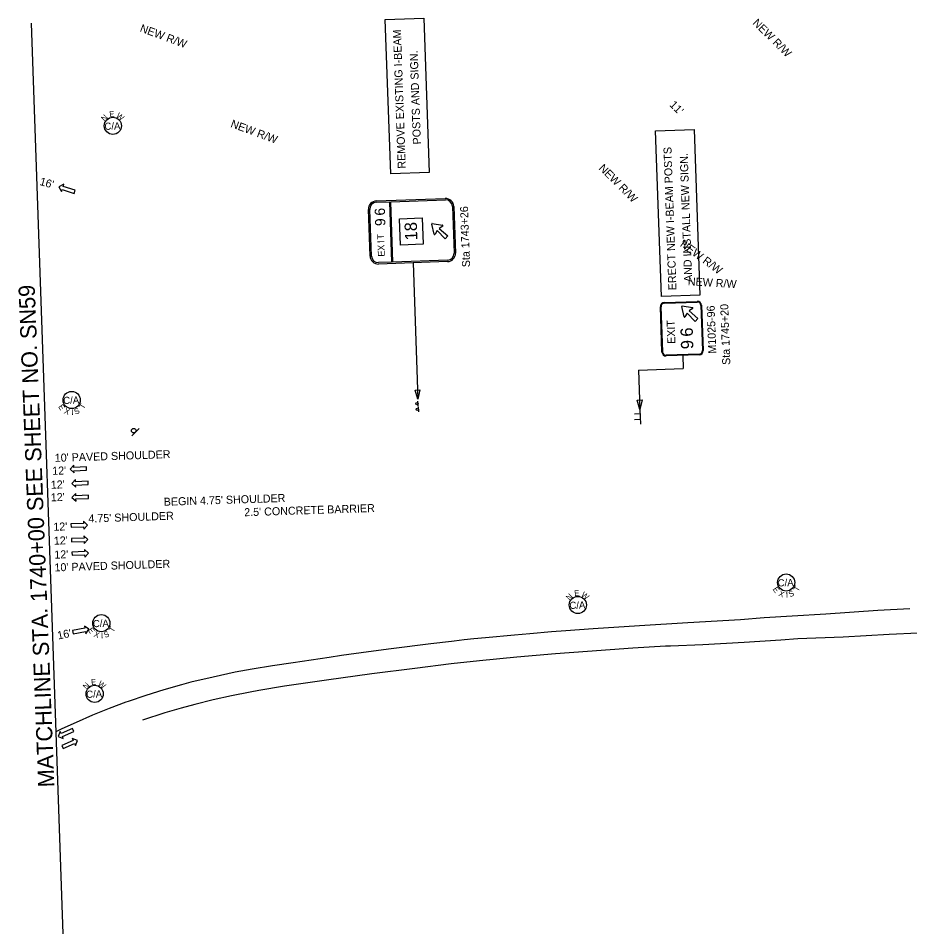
# Model space of a CAD drawing. Extents: x 1820452 to 1822009, y 1192445 to 1193332.
# Drawn here: x 1820452 to 1821231, y 1192445 to 1193246 of the extents above; entities that cross this region are included whole.
import ezdxf

# ---------------------------------------------------------------- set-up
doc = ezdxf.new("R2010")
doc.units = 0
for name, color, linetype in [('RD_EX_Road', 7, 'Continuous'), ('RD_PD_Final_LnLine', 7, 'Continuous'), ('RD_PD_Final_TX', 7, 'Continuous'), ('RD_PD_RW_TX', 7, 'Continuous'), ('RD_SHT_MatchLine', 7, 'Continuous'), ('RD_SHT_TX', 7, 'Continuous'), ('RD_Sketch10', 7, 'Continuous'), ('RD_Sketch8', 7, 'Continuous'), ('SN_P_Signs', 7, 'Continuous')]:
    doc.layers.add(name, color=color, linetype=linetype)

# ---------------------------------------------------------------- blocks, each defined once
blk = doc.blocks.new('SARRW2')
at = {"layer": 'RD_PD_Final_LnLine'}
blk.add_lwpolyline([(-12, 1.2), (-12, -1.2), (-2.83, -1.2), (-2.83, -2.83), (0, 0), (-2.83, 2.83), (-2.83, 1.2)], close=True, dxfattribs=at)

msp = doc.modelspace()

# ---------------------------------------------------------------- linework, layer by layer
at = {"layer": 'RD_EX_Road'}
for points in [[(1821230.79, 1192729.52), (1821202.71, 1192728.07), (1821157.28, 1192724.67), (1821127.76, 1192723.07), (1821103.32, 1192721.42), (1821082.58, 1192719.82), (1821036.79, 1192717.14), (1820994.41, 1192714.5), (1820953.78, 1192712.02), (1820929.96, 1192710.3), (1820917.49, 1192709.32), (1820898.46, 1192707.66), (1820885.17, 1192706.38), (1820859.77, 1192704.09), (1820849.75, 1192703.24), (1820841.08, 1192702.29), (1820832.43, 1192701.15), (1820830.07, 1192700.8), (1820812.05, 1192698.78), (1820777.32, 1192694.56), (1820757.63, 1192691.82), (1820733.93, 1192688.45), (1820723.23, 1192686.94), (1820691.67, 1192682.18), (1820673.81, 1192679.66), (1820656.01, 1192676.74), (1820641.19, 1192674.01), (1820621.77, 1192669.77), (1820602.43, 1192665.14), (1820594.24, 1192663.06), (1820578.6, 1192658.56), (1820563.08, 1192653.69), (1820547.67, 1192648.44), (1820545.4, 1192647.63), (1820530.83, 1192642.16), (1820516.39, 1192636.33), (1820502.12, 1192630.13), (1820489.64, 1192624.36), (1820484.41, 1192621.87)], [(1821237.87, 1192707.98), (1821212.68, 1192706.86), (1821172.45, 1192704.59), (1821132.84, 1192703.05), (1821117.99, 1192702.01), (1821085.93, 1192700.06), (1821049.67, 1192698.05), (1821021.61, 1192696.81), (1821017.07, 1192696.65), (1821002.85, 1192695.99), (1820988.64, 1192695.14), (1820968.74, 1192693.61), (1820948.83, 1192692.08), (1820920.97, 1192689.94), (1820887.31, 1192687.18), (1820854.66, 1192683.8), (1820829.77, 1192681.23), (1820798.11, 1192677.36), (1820760.55, 1192672.5), (1820720.98, 1192666.96), (1820706.53, 1192665.01), (1820684.1, 1192661.66), (1820661.72, 1192657.91), (1820654.08, 1192656.53), (1820637.94, 1192653.32), (1820621.88, 1192649.73), (1820605.9, 1192645.75), (1820594, 1192642.58), (1820579.73, 1192638.4), (1820560.24, 1192632.13)]]:
    msp.add_lwpolyline(points, dxfattribs=at)
at = {"layer": 'RD_SHT_MatchLine'}
msp.add_line((1820462.69, 1193241.52), (1820490.6, 1192445.3), dxfattribs=at)
at = {"layer": 'RD_Sketch10'}
for centre in [(1820534.23, 1193151.77), (1820940.54, 1192732.77), (1820518.3, 1192655.02)]:
    msp.add_circle(centre, 7.5, dxfattribs=at)
at = {"layer": 'RD_Sketch8'}
for centre in [(1820498.21, 1192912.02), (1821122.56, 1192752.43), (1820524.13, 1192716.82)]:
    msp.add_circle(centre, 7.5, dxfattribs=at)
at = {"layer": 'SN_P_Signs'}
for p, q in [((1820772.24, 1193244.66), (1820805.84, 1193245.83)), ((1820776.98, 1193109.72), (1820772.24, 1193244.66)), ((1820805.84, 1193245.83), (1820810.57, 1193110.9)), ((1821008.47, 1193147.36), (1821042.07, 1193148.54)), ((1821013.55, 1193002.43), (1821008.47, 1193147.36)), ((1821042.07, 1193148.54), (1821047.15, 1193003.61)), ((1820810.57, 1193110.9), (1820776.98, 1193109.72)), ((1820764.47, 1193086.13), (1820824.7, 1193088.24)), ((1820758.95, 1193037.91), (1820757.52, 1193078.68)), ((1820784.82, 1193070.61), (1820804.49, 1193071.3)), ((1820804.49, 1193071.3), (1820805.3, 1193048.24)), ((1820805.3, 1193048.24), (1820785.62, 1193047.55)), ((1820826.59, 1193034.27), (1820778.95, 1193032.6)), ((1820777.75, 1193032.56), (1820766.36, 1193032.16)), ((1820826.63, 1193033.07), (1820766.4, 1193030.96)), ((1820796.52, 1193032.02), (1820800.7, 1192912.67)), ((1821047.15, 1193003.61), (1821013.55, 1193002.43)), ((1821016.14, 1192997.3), (1821044.92, 1192998.31)), ((1821016.16, 1192996.7), (1821044.94, 1192997.71)), ((1821048.05, 1192994.82), (1821049.43, 1192955.24)), ((1821048.65, 1192994.84), (1821050.03, 1192955.26)), ((1821014.06, 1192954), (1821012.67, 1192993.58)), ((1821014.66, 1192954.02), (1821013.27, 1192993.6)), ((1821046.54, 1192952.14), (1821017.76, 1192951.13)), ((1821046.56, 1192951.54), (1821017.78, 1192950.53)), ((1821032.17, 1192951.04), (1821032.58, 1192939.49)), ((1820993.64, 1192938.12), (1821032.58, 1192939.49)), ((1820993.64, 1192938.12), (1820994.84, 1192903.83)), ((1820800.99, 1192906.55), (1820800.83, 1192911.05)), ((1820801.44, 1192901.68), (1820801.29, 1192906.18)), ((1820994.98, 1192899.93), (1820989.99, 1192899.75)), ((1820994.84, 1192903.83), (1820995.3, 1192890.8)), ((1820995.16, 1192894.91), (1820990.17, 1192894.74)), ((1820550.69, 1192880.6), (1820557.05, 1192886.97))]:
    msp.add_line(p, q, dxfattribs=at)
for points in [[(1820764.51, 1193084.93), (1820775.9, 1193085.33)], [(1820775.9, 1193085.33), (1820777.75, 1193032.56)], [(1820777.1, 1193085.37), (1820824.74, 1193087.04)], [(1820778.95, 1193032.6), (1820777.1, 1193085.37)], [(1820760.15, 1193037.95), (1820758.72, 1193078.72)], [(1820830.95, 1193081.25), (1820832.38, 1193040.48)], [(1820832.15, 1193081.3), (1820833.58, 1193040.52)], [(1820785.62, 1193047.55), (1820784.82, 1193070.61)], [(1820814.9, 1193057.06), (1820812.84, 1193065.85)], [(1820813.35, 1193066.4), (1820822.26, 1193064.96)], [(1820817.51, 1193060.16), (1820815.73, 1193056.95)], [(1820827.01, 1193055.61), (1820824.56, 1193052.98), (1820817.51, 1193060.16)], [(1820822.43, 1193064.14), (1820819.35, 1193062.13)], [(1820819.35, 1193062.13), (1820827.01, 1193055.61)], [(1821033.33, 1192984.9), (1821031.27, 1192993.69)], [(1821031.78, 1192994.24), (1821040.69, 1192992.8)], [(1821035.94, 1192988), (1821034.16, 1192984.79)], [(1821045.44, 1192983.45), (1821042.99, 1192980.82), (1821035.94, 1192988)], [(1821040.87, 1192991.98), (1821037.79, 1192989.98)], [(1821037.79, 1192989.98), (1821045.44, 1192983.45)]]:
    msp.add_lwpolyline(points, dxfattribs=at)
for points in [[(1820802.33, 1192920.96), (1820800.66, 1192912.67), (1820798.23, 1192920.77)], [(1820996.61, 1192912.1), (1820994.84, 1192903.83), (1820992.51, 1192911.96)]]:
    msp.add_lwpolyline(points, close=True, dxfattribs=at)
for centre, radius in [((1820799.9, 1192908.77), 1), ((1820800.35, 1192903.9), 1), ((1820552.45, 1192885.23), 2)]:
    msp.add_circle(centre, radius, dxfattribs=at)
for centre, radius, start, end in [((1820764.72, 1193078.93), 7.2, 92.00775, 182.00775), ((1820764.72, 1193078.93), 6, 92.00775, 182.00775), ((1820824.95, 1193081.04), 7.2, 2.00775, 92.00775), ((1820824.95, 1193081.04), 6, 2.00775, 92.00775), ((1820813.28, 1193065.95), 0.45, 80.82985, 193.18565), ((1820822.19, 1193064.51), 0.45, 303.04565, 80.82985), ((1820815.34, 1193057.16), 0.45, 193.18565, 330.96985), ((1820766.15, 1193038.16), 7.2, 182.00775, 272.00775), ((1820766.15, 1193038.16), 6, 182.00775, 272.00775), ((1820826.38, 1193040.27), 6, 272.00775, 2.00775), ((1820826.38, 1193040.27), 7.2, 272.00775, 2.00775), ((1821016.27, 1192993.7), 3.6, 92.00775, 182.00775), ((1821016.27, 1192993.7), 3, 92.00775, 182.00775), ((1821031.71, 1192993.8), 0.45, 80.82985, 193.18565), ((1821045.05, 1192994.71), 3.6, 2.00775, 92.00775), ((1821045.05, 1192994.71), 3, 2.00775, 92.00775), ((1821040.62, 1192992.36), 0.45, 303.04565, 80.82985), ((1821033.77, 1192985.01), 0.45, 193.18565, 330.96985), ((1821017.65, 1192954.13), 3.6, 182.00775, 272.00775), ((1821017.65, 1192954.13), 3, 182.00775, 272.00775), ((1821046.44, 1192955.14), 3, 272.00775, 2.00775), ((1821046.44, 1192955.14), 3.6, 272.00775, 2.00775)]:
    msp.add_arc(centre, radius, start, end, dxfattribs=at)

# ---------------------------------------------------------------- block references
at = {"layer": 'RD_PD_Final_LnLine'}
for p, xscale, yscale, rotation in [((1820487.01, 1193098.52), 1.2000000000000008, 1.2000000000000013, 162.01187164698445), ((1820496.76, 1192851.5), 1.2000000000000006, 1.2000000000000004, -177.99225385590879), ((1820498.25, 1192838.97), 1.2000000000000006, 1.2000000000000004, -177.99225385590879), ((1820498.48, 1192826.79), 1.2000000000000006, 1.2000000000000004, -177.99225385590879), ((1820511.98, 1192802.69), 1.2000000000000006, 1.2000000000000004, 2.007746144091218), ((1820512.43, 1192789.93), 1.2000000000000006, 1.2000000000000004, 2.007746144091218), ((1820512.84, 1192778.13), 1.2000000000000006, 1.2000000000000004, 2.007746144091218), ((1820513.33, 1192711.63), 1.2000000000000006, 1.2000000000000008, 10.759883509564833), ((1820486.39, 1192617.76), 1.200000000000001, 1.2000000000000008, -156.3367253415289), ((1820503.25, 1192614.27), 1.2000000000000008, 1.2000000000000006, 23.663274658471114)]:
    msp.add_blockref('SARRW2', p, dxfattribs=dict(at, xscale=xscale, yscale=yscale, rotation=rotation))

# ---------------------------------------------------------------- texts
at = {"layer": 'RD_PD_Final_TX'}
for s, rotation, p in [("11'", 314.362, (1821020.17, 1193169.74)), ("16'", 344.35067, (1820469.71, 1193100.18)), ("10' PAVED SHOULDER", 1.88215, (1820483.54, 1192857.91)), ("12'", 2.21438, (1820481.35, 1192846.52)), ("12'", 2.21438, (1820480.08, 1192834.36)), ("12'", 2.21438, (1820480.07, 1192823.34)), ("BEGIN 4.75' SHOULDER", 1.81219, (1820578.75, 1192819.51)), ("2.5' CONCRETE BARRIER", 1.88215, (1820649.11, 1192810.35)), ("4.75' SHOULDER", 2.00775, (1820512.96, 1192804.8)), ("12'", 2.21438, (1820482.32, 1192797.6)), ("12'", 2.21438, (1820482.75, 1192785.42)), ("12'", 2.21438, (1820483.17, 1192773.23)), ("10' PAVED SHOULDER", 1.88215, (1820483.29, 1192762.07)), ("16'", 11.63504, (1820486.41, 1192702.54))]:
    msp.add_text(s, height=7, rotation=rotation, dxfattribs=at).set_placement(p)
at = {"layer": 'RD_PD_RW_TX'}
for rotation, p in [(315.28229, (1821092.79, 1193241.25)), (339.70698, (1820557.29, 1193234.42)), (339.70698, (1820636.51, 1193150.88)), (315.28229, (1820958.3, 1193114.15)), (323.47463, (1821029.29, 1193046.95)), (356.42493, (1821036.5, 1193012.5))]:
    msp.add_text('NEW R/W', height=7, rotation=rotation, dxfattribs=at).set_placement(p)
at = {"layer": 'RD_SHT_TX'}
msp.add_text('MATCHLINE STA. 1740+00 SEE SHEET NO. SN59', height=14.1726, rotation=92.25659, dxfattribs=at).set_placement((1820483.15, 1192573.6))
at = {"layer": 'RD_Sketch10'}
for s, height, rotation, p in [('N', 5, 46.87751, (1820526.98, 1193155.35)), ('E', 5, 6.3408, (1820531.4, 1193159.38)), ('W', 5, 321.31036, (1820536.57, 1193159.81)), ('C/A', 6.25, 2.00775, (1820526.94, 1193148.23)), ('E', 5, 6.3408, (1820937.71, 1192740.38)), ('N', 5, 46.87751, (1820933.29, 1192736.35)), ('W', 5, 321.31036, (1820942.88, 1192740.81)), ('C/A', 6.25, 2.00775, (1820933.25, 1192729.23)), ('E', 5, 6.3408, (1820515.46, 1192662.63)), ('W', 5, 321.31036, (1820520.64, 1192663.06)), ('N', 5, 46.87751, (1820511.04, 1192658.6)), ('C/A', 6.25, 2.00775, (1820511, 1192651.48))]:
    msp.add_text(s, height=height, rotation=rotation, dxfattribs=at).set_placement(p)
at = {"layer": 'RD_Sketch8'}
for s, height, rotation, p in [('C/A', 6.25, 2.00775, (1820490.92, 1192908.48)), ('E', 5, 305.21899, (1820486.19, 1192906.07)), ('T', 5, 60.19289, (1820508.7, 1192903.67)), ('X', 5, 337.64836, (1820491.17, 1192900.59)), ('I', 5, 1.80836, (1820498.02, 1192898.76)), ('S', 5, 23.80019, (1820501.66, 1192899.06)), ('C/A', 6.25, 2.00775, (1821115.26, 1192748.89)), ('E', 5, 305.21899, (1821110.54, 1192746.48)), ('T', 5, 60.19289, (1821133.05, 1192744.08)), ('X', 5, 337.64836, (1821115.51, 1192741)), ('I', 5, 1.80836, (1821122.36, 1192739.17)), ('S', 5, 23.80019, (1821126.01, 1192739.47)), ('C/A', 6.25, 2.00775, (1820516.83, 1192713.28)), ('T', 5, 60.19289, (1820534.62, 1192708.47)), ('E', 5, 305.21899, (1820512.11, 1192710.87)), ('X', 5, 337.64836, (1820517.08, 1192705.39)), ('I', 5, 1.80836, (1820523.93, 1192703.56)), ('S', 5, 23.80019, (1820527.58, 1192703.86))]:
    msp.add_text(s, height=height, rotation=rotation, dxfattribs=at).set_placement(p)
at = {"layer": 'SN_P_Signs'}
for s, height, rotation, p in [('REMOVE EXISTING I-BEAM', 6.9998, 92.00783, (1820790.18, 1193114.48)), ('POSTS AND SIGN.', 6.9998, 92.00783, (1820803.44, 1193135.66)), ('ERECT NEW I-BEAM POSTS', 6.9998, 92.00783, (1821026.72, 1193008.13)), ('AND INSTALL NEW SIGN.', 6.9998, 92.00783, (1821040.48, 1193015.31)), ('6', 9, 92.00775, (1820772.12, 1193073.45)), ('Sta 1743+26', 7, 92.00783, (1820846.39, 1193028.27)), ('9', 9, 92.00775, (1820772.44, 1193064.35)), ('18', 10.8, 92.00775, (1820800.34, 1193051.78)), ('T', 6, 92.00775, (1820771.35, 1193052.43)), ('I', 6, 92.00775, (1820771.46, 1193049.45)), ('X', 6, 92.00775, (1820771.7, 1193042.64)), ('E', 6, 92.00775, (1820771.88, 1193037.49)), ('M1025-96', 7, 92.00783, (1821061.55, 1192952.7)), ('Sta 1745+20', 7, 92.00783, (1821073.8, 1192942.82)), ('EXIT', 7, 92.00775, (1821025.81, 1192961.22)), ('6', 10.8, 92.00775, (1821041.2, 1192967.56)), ('9', 10.8, 92.00775, (1821041.58, 1192956.64))]:
    msp.add_text(s, height=height, rotation=rotation, dxfattribs=at).set_placement(p)

doc.saveas('drawing.dxf')
